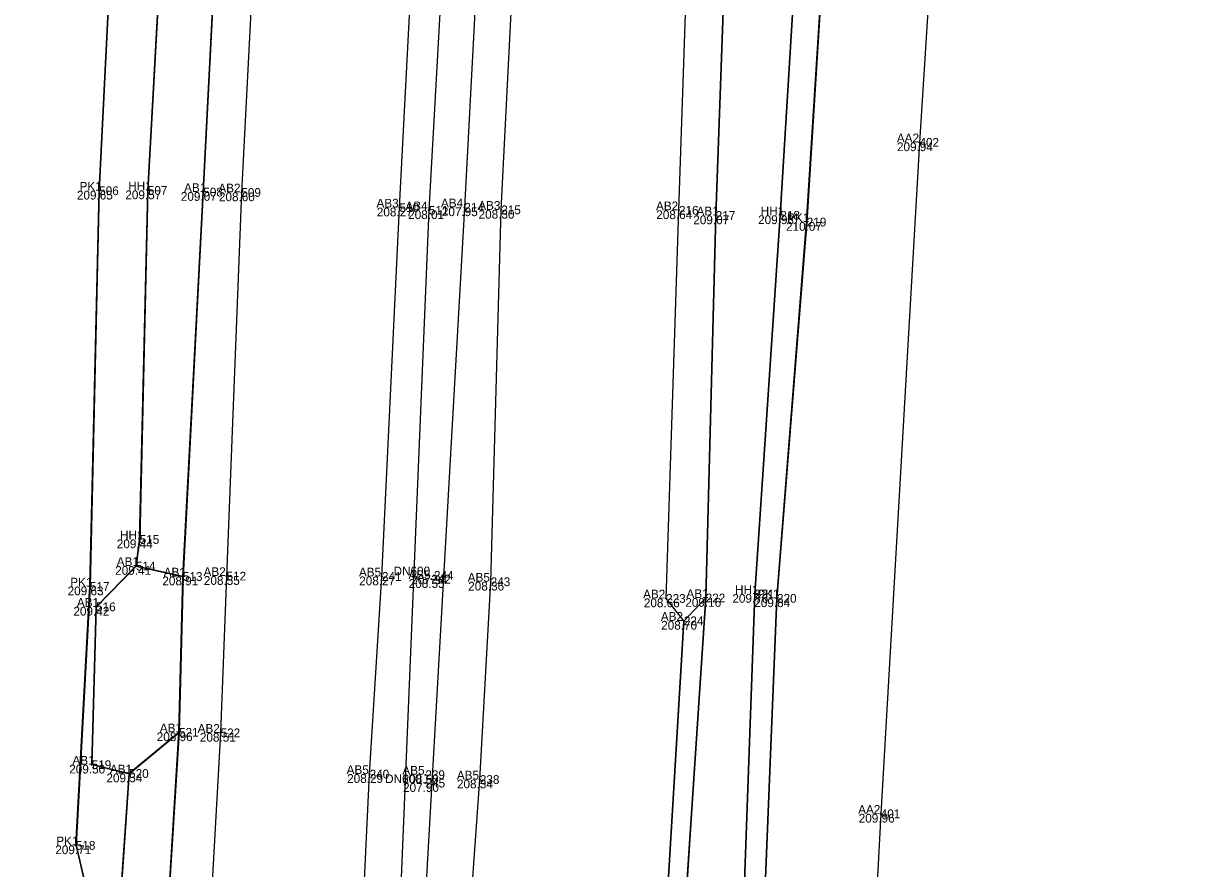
# Model space of a CAD drawing. Extents: x -262982 to -262706, y -1238714 to -1237093.
# Drawn here: x -262835.54 to -262808.76, y -1237921.73 to -1237902.47 of the extents above; entities that cross this region are included whole.
import ezdxf

# ---------------------------------------------------------------- set-up
doc = ezdxf.new("R2010")
doc.units = 0
for name, color, linetype in [('01_Hrana_betónu', 7, 'Continuous'), ('02_Oplotenie', 7, 'Continuous'), ('03_Asfalt', 7, 'Continuous'), ('05_Hrana_terénu', 7, 'Continuous'), ('07_Iné', 7, 'Continuous'), ('09_Múrik', 7, 'Continuous'), ('Groma (21)', 7, 'Continuous'), ('Groma (22)', 7, 'Continuous'), ('Groma (23)', 7, 'Continuous'), ('Groma (24)', 7, 'Continuous'), ('U004_Asfalty', 7, 'Continuous'), ('U004_Betónové_múriky', 7, 'Continuous'), ('U004_Betónové_panely', 7, 'Continuous'), ('U004_Betóny_prídavné', 7, 'Continuous'), ('U004_Zeleň_mimo', 7, 'Continuous'), ('U004_Zeleň_vnútro', 7, 'Continuous'), ('U004_Zeleň_zatrávňovač', 7, 'Continuous')]:
    doc.layers.add(name, color=color, linetype=linetype)

msp = doc.modelspace()

# ---------------------------------------------------------------- linework, layer by layer
at = {"layer": '01_Hrana_betónu'}
for points in [[(-262833.49, -1237932.513), (-262832.358, -1237924.572), (-262831.993, -1237918.626), (-262831.904, -1237915.074), (-262831.439, -1237906.309), (-262830.324, -1237884.482), (-262828.859, -1237869.656), (-262826.973, -1237856.487), (-262824.752, -1237845.872), (-262820.768, -1237827.409), (-262815.971, -1237805.011), (-262811.874, -1237785.528), (-262810.073, -1237767.205), (-262809.465, -1237744.209), (-262809.348, -1237719.32), (-262807.762, -1237709.127), (-262805.583, -1237701.261), (-262801.096, -1237689.829), (-262795.064, -1237676.268)], [(-262794.181, -1237676.612), (-262800.21, -1237690.201), (-262804.735, -1237701.618), (-262806.814, -1237709.415), (-262808.46, -1237719.391), (-262808.589, -1237744.23), (-262809.169, -1237767.262), (-262810.977, -1237785.858), (-262815.119, -1237805.286), (-262819.878, -1237827.449), (-262823.898, -1237846.237), (-262826.14, -1237856.747), (-262827.996, -1237869.725), (-262829.453, -1237884.611), (-262830.572, -1237906.318), (-262830.909, -1237915.064), (-262831.044, -1237918.638), (-262831.379, -1237924.623), (-262832.499, -1237932.636), (-262832.416, -1237932.646)], [(-262828.366, -1237932.946), (-262828.106, -1237929.217), (-262827.649, -1237919.578), (-262827.369, -1237915.073), (-262826.968, -1237906.664), (-262825.835, -1237884.909), (-262824.318, -1237870.338), (-262822.252, -1237856.88), (-262820.394, -1237847.242), (-262816.344, -1237828.005), (-262811.527, -1237806.128), (-262807.485, -1237786.652), (-262805.817, -1237767.526), (-262804.904, -1237743.876), (-262804.544, -1237721.54), (-262802.773, -1237710.111), (-262800.948, -1237703.699), (-262796.578, -1237692.416), (-262790.297, -1237678.834), (-262789.671, -1237677.512)], [(-262788.862, -1237677.903), (-262789.612, -1237679.5), (-262795.758, -1237692.783), (-262800.102, -1237704.105), (-262801.904, -1237710.319), (-262803.638, -1237721.631), (-262804.041, -1237743.855), (-262804.886, -1237767.666), (-262806.567, -1237786.84), (-262810.653, -1237806.707), (-262815.575, -1237828.361), (-262819.614, -1237847.41), (-262821.404, -1237856.927), (-262823.638, -1237870.532), (-262825.083, -1237884.947), (-262826.299, -1237906.725), (-262827.242, -1237929.453), (-262827.527, -1237933.008)], [(-262788.441, -1237678.106), (-262789.499, -1237680.304), (-262796.488, -1237695.789), (-262799.561, -1237704.378), (-262801.599, -1237711.648), (-262803.17, -1237722.277), (-262803.523, -1237744.912), (-262804.331, -1237767.555), (-262806.033, -1237786.907), (-262810.428, -1237808.027), (-262815.321, -1237829.941), (-262818.5, -1237845.545), (-262820.865, -1237857.635), (-262822.962, -1237871.266), (-262824.386, -1237885.795), (-262825.49, -1237906.658), (-262826.835, -1237930.337), (-262826.931, -1237933.053)], [(-262825.987, -1237933.123), (-262825.899, -1237930.36), (-262825.137, -1237919.703), (-262824.89, -1237915.193), (-262824.65, -1237906.715), (-262823.596, -1237885.855), (-262822.137, -1237871.403), (-262820.061, -1237857.781), (-262817.692, -1237845.812), (-262814.459, -1237830.149), (-262809.645, -1237808.205), (-262805.191, -1237787.117), (-262803.484, -1237767.641), (-262802.568, -1237744.998), (-262802.266, -1237722.317), (-262800.862, -1237712.121), (-262798.805, -1237704.616), (-262795.791, -1237696.17), (-262788.393, -1237679.964), (-262787.674, -1237678.477)], [(-262783.803, -1237680.361), (-262791.072, -1237697.733), (-262794.156, -1237706.196), (-262796.111, -1237713.494), (-262797.353, -1237722.795), (-262798.006, -1237745.028), (-262798.995, -1237767.834), (-262800.837, -1237788.066), (-262805.174, -1237808.895), (-262810.048, -1237831.05), (-262813.207, -1237846.368), (-262815.438, -1237858.025), (-262817.519, -1237871.503), (-262819.01, -1237885.889), (-262819.761, -1237906.843), (-262819.991, -1237915.564)], [(-262820.488, -1237916.085), (-262820.893, -1237915.574), (-262820.599, -1237906.725), (-262819.894, -1237885.916), (-262818.364, -1237871.361), (-262816.365, -1237858.042), (-262814.122, -1237846.343), (-262810.891, -1237830.85), (-262806.137, -1237808.69), (-262801.736, -1237787.923), (-262799.952, -1237767.772), (-262798.979, -1237744.912), (-262798.159, -1237722.635), (-262796.927, -1237713.21), (-262795.035, -1237705.927), (-262791.963, -1237697.425), (-262785.076, -1237681.215)]]:
    msp.add_lwpolyline(points, dxfattribs=at)
at = {"layer": '02_Oplotenie'}
for points in [[(-262834.343, -1237921.203), (-262834.024, -1237915.302), (-262833.812, -1237906.279), (-262832.732, -1237884.616), (-262831.151, -1237869.343), (-262829.251, -1237856.325), (-262826.951, -1237845.31), (-262823.094, -1237827.731), (-262817.951, -1237804.339), (-262814.023, -1237784.135), (-262812.336, -1237767.05), (-262811.754, -1237744.594), (-262811.555, -1237719.093), (-262809.863, -1237708.888), (-262807.835, -1237700.632), (-262803.244, -1237689.13), (-262797.291, -1237676.038)], [(-262782.476, -1237683.046), (-262789.338, -1237700.035), (-262791.92, -1237707.468), (-262793.68, -1237714.792), (-262794.853, -1237723.195), (-262795.698, -1237745.299), (-262796.564, -1237768.081), (-262798.719, -1237788.188), (-262802.852, -1237809.448), (-262807.527, -1237831.589), (-262810.764, -1237846.834), (-262812.842, -1237857.763), (-262814.888, -1237871.127), (-262816.319, -1237886.182), (-262816.945, -1237895.233), (-262817.687, -1237906.993), (-262818.366, -1237915.571), (-262818.764, -1237925.136)]]:
    msp.add_lwpolyline(points, dxfattribs=at)
at = {"layer": '03_Asfalt'}
msp.add_lwpolyline([(-262814.5, -1237895.481), (-262815.119, -1237905.177), (-262816.001, -1237920.483), (-262816.76, -1237934.791)], dxfattribs=at)
at = {"layer": '05_Hrana_terénu'}
for points in [[(-262796.037, -1237675.468), (-262802.307, -1237689.303), (-262806.908, -1237700.928), (-262808.861, -1237708.991), (-262810.491, -1237719.246), (-262810.648, -1237744.371), (-262811.212, -1237767.185), (-262812.78, -1237784.48), (-262817.048, -1237804.549), (-262821.958, -1237827.467), (-262825.893, -1237845.536), (-262828.436, -1237856.363), (-262830.087, -1237869.518), (-262831.495, -1237884.449), (-262832.703, -1237906.272), (-262832.889, -1237914.228), (-262832.974, -1237914.835)], [(-262819.123, -1237925.833), (-262819.193, -1237924.361), (-262818.874, -1237915.472), (-262818.289, -1237906.84), (-262817.033, -1237886.241), (-262815.506, -1237871.209), (-262813.693, -1237857.604), (-262811.493, -1237846.649), (-262808.389, -1237831.401), (-262803.328, -1237809.401), (-262799.108, -1237788.219), (-262797.264, -1237767.972), (-262796.32, -1237745.233), (-262795.609, -1237723.113), (-262794.587, -1237714.488), (-262792.775, -1237707.13), (-262790.198, -1237699.936), (-262783.238, -1237683.427), (-262781.933, -1237681.667), (-262781.499, -1237681.254)], [(-262833.13, -1237919.565), (-262833.486, -1237924.805), (-262834.418, -1237925.991)]]:
    msp.add_lwpolyline(points, dxfattribs=at)
at = {"layer": '07_Iné'}
msp.add_lwpolyline([(-262831.993, -1237918.626), (-262833.13, -1237919.565), (-262833.983, -1237919.364), (-262833.882, -1237915.765), (-262832.974, -1237914.835), (-262831.904, -1237915.074)], dxfattribs=at)
at = {"layer": '09_Múrik'}
for points in [[(-262819.991, -1237915.564), (-262820.655, -1237925.75), (-262821.327, -1237933.476)], [(-262821.581, -1237933.453), (-262821.074, -1237925.854), (-262820.488, -1237916.085)]]:
    msp.add_lwpolyline(points, dxfattribs=at)
at = {"layer": 'Groma (21)'}
for centre in [(-262815.119, -1237905.177), (-262833.812, -1237906.279), (-262832.703, -1237906.272), (-262831.439, -1237906.309), (-262830.572, -1237906.318), (-262826.968, -1237906.664), (-262826.299, -1237906.725), (-262825.49, -1237906.658), (-262824.65, -1237906.715), (-262820.599, -1237906.725), (-262819.761, -1237906.843), (-262818.289, -1237906.84), (-262817.687, -1237906.993), (-262832.889, -1237914.228), (-262832.974, -1237914.835), (-262826.182, -1237915.048), (-262834.024, -1237915.302), (-262831.904, -1237915.074), (-262830.909, -1237915.064), (-262827.369, -1237915.073), (-262826.241, -1237915.133), (-262824.89, -1237915.193), (-262820.893, -1237915.574), (-262819.991, -1237915.564), (-262818.874, -1237915.472), (-262818.366, -1237915.571), (-262833.882, -1237915.765), (-262820.488, -1237916.085), (-262831.993, -1237918.626), (-262831.044, -1237918.638), (-262833.983, -1237919.364), (-262833.13, -1237919.565), (-262827.649, -1237919.578), (-262826.379, -1237919.592), (-262826.375, -1237919.783), (-262825.137, -1237919.703), (-262816.001, -1237920.483), (-262834.343, -1237921.203)]:
    msp.add_circle(centre, 0.01, dxfattribs=at)
at = {"layer": 'U004_Asfalty'}
msp.add_lwpolyline([(-262818.76, -1237925.14), (-262818.37, -1237915.57), (-262817.69, -1237906.99), (-262816.95, -1237895.23), (-262814.5, -1237895.48), (-262815.12, -1237905.18), (-262816, -1237920.48), (-262816.76, -1237934.79), (-262818.3, -1237934.7), (-262817.69, -1237925.58)], close=True, dxfattribs=at)
at = {"layer": 'U004_Betónové_múriky'}
msp.add_lwpolyline([(-262820.66, -1237925.75), (-262821.33, -1237933.48), (-262821.58, -1237933.45), (-262821.07, -1237925.85), (-262820.49, -1237916.09), (-262819.99, -1237915.56)], close=True, dxfattribs=at)
at = {"layer": 'U004_Betónové_panely'}
msp.add_lwpolyline([(-262815.44, -1237858.03), (-262817.52, -1237871.5), (-262819.01, -1237885.89), (-262819.76, -1237906.84), (-262819.99, -1237915.56), (-262820.49, -1237916.09), (-262821.07, -1237925.85), (-262821.58, -1237933.45), (-262821.86, -1237933.43), (-262822, -1237934.47), (-262826.02, -1237934.23), (-262826.97, -1237934.17), (-262827.62, -1237934.13), (-262828.45, -1237934.08), (-262832.51, -1237933.84), (-262832.42, -1237932.65), (-262832.5, -1237932.64), (-262833.49, -1237932.51), (-262832.36, -1237924.57), (-262831.99, -1237918.63), (-262831.9, -1237915.07), (-262831.44, -1237906.31), (-262830.32, -1237884.48), (-262828.86, -1237869.66)], dxfattribs=at)
at = {"layer": 'U004_Betóny_prídavné'}
msp.add_lwpolyline([(-262831.9, -1237915.07), (-262831.99, -1237918.63), (-262833.13, -1237919.57), (-262833.98, -1237919.36), (-262833.88, -1237915.77), (-262832.97, -1237914.84)], close=True, dxfattribs=at)
at = {"layer": 'U004_Zeleň_mimo'}
msp.add_lwpolyline([(-262831.15, -1237869.34), (-262832.73, -1237884.62), (-262833.81, -1237906.28), (-262834.02, -1237915.3), (-262834.34, -1237921.2), (-262833.49, -1237924.81), (-262834.42, -1237925.99), (-262837.15, -1237925.73), (-262837.41, -1237925.56), (-262839.28, -1237924.72), (-262838.95, -1237919.22), (-262848.49, -1237918.39), (-262860.57, -1237917.21), (-262859.39, -1237895.81), (-262865.89, -1237895.46), (-262864.07, -1237848.35)], dxfattribs=at)
at = {"layer": 'U004_Zeleň_vnútro'}
for points in [[(-262798.72, -1237788.19), (-262802.85, -1237809.45), (-262807.53, -1237831.59), (-262810.76, -1237846.83), (-262812.84, -1237857.76), (-262814.89, -1237871.13), (-262816.32, -1237886.18), (-262816.95, -1237895.23), (-262817.69, -1237906.99), (-262818.37, -1237915.57), (-262818.76, -1237925.14), (-262817.69, -1237925.58), (-262819.12, -1237925.83), (-262819.19, -1237924.36), (-262818.87, -1237915.47), (-262818.29, -1237906.84), (-262817.03, -1237886.24), (-262815.51, -1237871.21), (-262813.69, -1237857.6), (-262811.49, -1237846.65), (-262808.39, -1237831.4), (-262803.33, -1237809.4), (-262799.11, -1237788.22)], [(-262817.05, -1237804.55), (-262821.96, -1237827.47), (-262825.89, -1237845.54), (-262828.44, -1237856.36), (-262830.09, -1237869.52), (-262831.5, -1237884.45), (-262832.7, -1237906.27), (-262832.89, -1237914.23), (-262832.97, -1237914.84), (-262833.88, -1237915.77), (-262833.98, -1237919.36), (-262833.13, -1237919.57), (-262833.49, -1237924.81), (-262834.34, -1237921.2), (-262834.02, -1237915.3), (-262833.81, -1237906.28), (-262832.73, -1237884.62), (-262831.15, -1237869.34), (-262829.25, -1237856.33), (-262826.95, -1237845.31), (-262823.09, -1237827.73), (-262817.95, -1237804.34)]]:
    msp.add_lwpolyline(points, dxfattribs=at)
at = {"layer": 'U004_Zeleň_zatrávňovač'}
for points in [[(-262811.87, -1237785.53), (-262815.97, -1237805.01), (-262820.77, -1237827.41), (-262824.75, -1237845.87), (-262826.97, -1237856.49), (-262828.86, -1237869.66), (-262830.32, -1237884.48), (-262831.44, -1237906.31), (-262831.9, -1237915.07), (-262832.97, -1237914.84), (-262832.89, -1237914.23), (-262832.7, -1237906.27), (-262831.5, -1237884.45), (-262830.09, -1237869.52), (-262828.44, -1237856.36), (-262825.89, -1237845.54), (-262821.96, -1237827.47), (-262817.05, -1237804.55)], [(-262813.69, -1237857.6), (-262815.51, -1237871.21), (-262817.03, -1237886.24), (-262818.29, -1237906.84), (-262818.87, -1237915.47), (-262819.19, -1237924.36), (-262819.12, -1237925.83), (-262819.49, -1237933.29), (-262820.8, -1237933.2), (-262820.84, -1237933.52), (-262821.33, -1237933.48), (-262821.28, -1237933), (-262820.66, -1237925.75), (-262819.99, -1237915.56), (-262819.76, -1237906.84), (-262819.01, -1237885.89), (-262817.52, -1237871.5), (-262815.44, -1237858.03)]]:
    msp.add_lwpolyline(points, dxfattribs=at)
msp.add_lwpolyline([(-262834.42, -1237925.99), (-262833.49, -1237924.81), (-262833.13, -1237919.57), (-262831.99, -1237918.63), (-262832.36, -1237924.57), (-262833.46, -1237932.25), (-262834.77, -1237932.05)], close=True, dxfattribs=at)

# ---------------------------------------------------------------- texts
at = {"layer": 'Groma (22)'}
for s, p in [('402', (-262815.119, -1237905.277)), ('506', (-262833.812, -1237906.379)), ('507', (-262832.703, -1237906.372)), ('508', (-262831.439, -1237906.409)), ('509', (-262830.572, -1237906.418)), ('510', (-262826.968, -1237906.764)), ('511', (-262826.299, -1237906.825)), ('214', (-262825.49, -1237906.758)), ('215', (-262824.65, -1237906.815)), ('216', (-262820.599, -1237906.825)), ('217', (-262819.761, -1237906.943)), ('218', (-262818.289, -1237906.94)), ('219', (-262817.687, -1237907.093)), ('515', (-262832.889, -1237914.328)), ('514', (-262832.974, -1237914.935)), ('513', (-262831.904, -1237915.174)), ('512', (-262830.909, -1237915.164)), ('241', (-262827.369, -1237915.173)), ('242', (-262826.241, -1237915.233)), ('244', (-262826.182, -1237915.148)), ('517', (-262834.024, -1237915.402)), ('243', (-262824.89, -1237915.293)), ('223', (-262820.893, -1237915.674)), ('222', (-262819.991, -1237915.664)), ('221', (-262818.874, -1237915.572)), ('220', (-262818.366, -1237915.671)), ('516', (-262833.882, -1237915.865)), ('224', (-262820.488, -1237916.185)), ('521', (-262831.993, -1237918.726)), ('522', (-262831.044, -1237918.738)), ('519', (-262833.983, -1237919.464)), ('520', (-262833.13, -1237919.665)), ('240', (-262827.649, -1237919.678)), ('239', (-262826.379, -1237919.692)), ('245', (-262826.375, -1237919.883)), ('238', (-262825.137, -1237919.803)), ('401', (-262816.001, -1237920.583)), ('518', (-262834.343, -1237921.303))]:
    msp.add_text(s, height=0.2, dxfattribs=at).set_placement(p)
at = {"layer": 'Groma (23)'}
for s, p in [('209.94', (-262815.631, -1237905.377)), ('209.65', (-262834.319, -1237906.479)), ('209.57', (-262833.216, -1237906.472)), ('209.07', (-262831.951, -1237906.509)), ('208.60', (-262831.083, -1237906.518)), ('208.27', (-262827.485, -1237906.864)), ('208.01', (-262826.771, -1237906.925)), ('207.95', (-262826.003, -1237906.858)), ('208.30', (-262825.166, -1237906.915)), ('208.64', (-262821.116, -1237906.925)), ('209.07', (-262820.273, -1237907.043)), ('209.93', (-262818.796, -1237907.04)), ('210.07', (-262818.16, -1237907.193)), ('209.44', (-262833.41, -1237914.428)), ('209.41', (-262833.447, -1237915.035)), ('207.94', (-262826.699, -1237915.248)), ('209.63', (-262834.531, -1237915.502)), ('208.91', (-262832.372, -1237915.274)), ('208.55', (-262831.426, -1237915.264)), ('208.27', (-262827.886, -1237915.273)), ('208.55', (-262826.758, -1237915.333)), ('208.36', (-262825.402, -1237915.393)), ('208.66', (-262821.4, -1237915.774)), ('209.16', (-262820.455, -1237915.764)), ('209.76', (-262819.382, -1237915.672)), ('209.84', (-262818.883, -1237915.771)), ('209.42', (-262834.399, -1237915.965)), ('208.70', (-262821.005, -1237916.285)), ('208.96', (-262832.5, -1237918.826)), ('208.51', (-262831.517, -1237918.838)), ('209.50', (-262834.494, -1237919.564)), ('209.54', (-262833.647, -1237919.765)), ('208.29', (-262828.161, -1237919.778)), ('208.50', (-262826.895, -1237919.792)), ('207.90', (-262826.887, -1237919.983)), ('208.34', (-262825.658, -1237919.903)), ('209.96', (-262816.503, -1237920.683)), ('209.71', (-262834.812, -1237921.403))]:
    msp.add_text(s, height=0.2, dxfattribs=at).set_placement(p)
at = {"layer": 'Groma (24)'}
for s, p in [('AA2', (-262815.634, -1237905.177)), ('PK1', (-262834.259, -1237906.279)), ('HH1', (-262833.15, -1237906.272)), ('AB1', (-262831.877, -1237906.309)), ('AB2', (-262831.096, -1237906.318)), ('AB3', (-262827.492, -1237906.664)), ('AB4', (-262826.024, -1237906.658)), ('AB4', (-262826.833, -1237906.725)), ('AB3', (-262825.174, -1237906.715)), ('AB2', (-262821.123, -1237906.725)), ('AB1', (-262820.199, -1237906.843)), ('HH1', (-262818.736, -1237906.84)), ('PK1', (-262818.134, -1237906.993)), ('HH1', (-262833.336, -1237914.228)), ('AB1', (-262833.412, -1237914.835)), ('AB1', (-262832.342, -1237915.074)), ('AB2', (-262831.433, -1237915.064)), ('AB5', (-262827.893, -1237915.073)), ('DN600', (-262827.103, -1237915.048)), ('AB5', (-262826.765, -1237915.133)), ('AB5', (-262825.414, -1237915.193)), ('PK1', (-262834.471, -1237915.302)), ('HH1', (-262819.321, -1237915.472)), ('AB1', (-262834.32, -1237915.765)), ('AB2', (-262821.417, -1237915.574)), ('AB1', (-262820.429, -1237915.564)), ('PK1', (-262818.813, -1237915.571)), ('AB2', (-262821.012, -1237916.085)), ('AB1', (-262832.431, -1237918.626)), ('AB2', (-262831.568, -1237918.638)), ('AB1', (-262834.421, -1237919.364)), ('AB1', (-262833.568, -1237919.565)), ('AB5', (-262828.173, -1237919.578)), ('DN600', (-262827.296, -1237919.783)), ('AB5', (-262826.903, -1237919.592)), ('AB5', (-262825.661, -1237919.703)), ('AA2', (-262816.516, -1237920.483)), ('PK1', (-262834.79, -1237921.203))]:
    msp.add_text(s, height=0.2, dxfattribs=at).set_placement(p)

doc.saveas('drawing.dxf')
